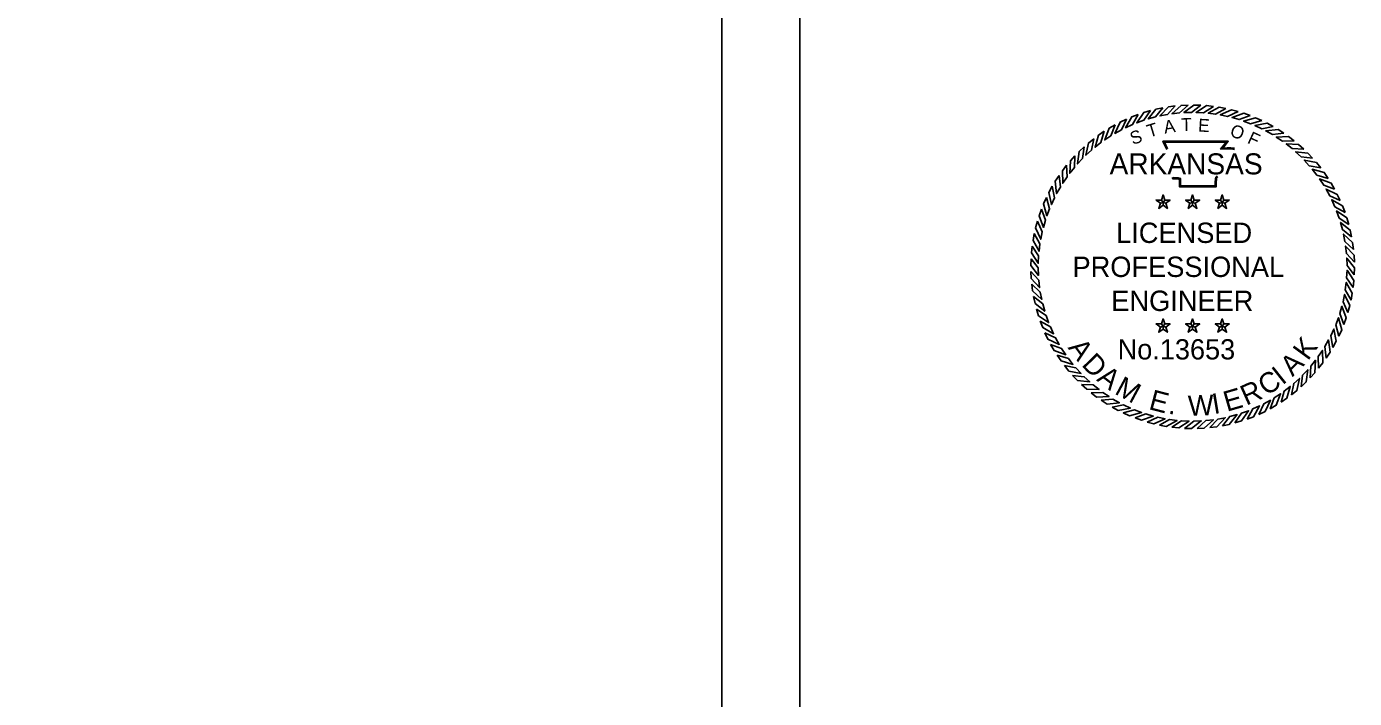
# Model space of a CAD drawing. Extents: x 759422 to 1467393, y 1662254 to 1691786.
# Drawn here: x 1466902.4 to 1467393.3, y 1691202.3 to 1691450.7 of the extents above; entities that cross this region are included whole.
import ezdxf

# ---------------------------------------------------------------- set-up
doc = ezdxf.new("R2010")
doc.units = 0
doc.layers.add('1', color=7, linetype='Continuous')
doc.layers.add('G-ANNO-STMP-AEW', color=7, linetype='Continuous')

msp = doc.modelspace()

# ---------------------------------------------------------------- linework, layer by layer
at = {"layer": '1'}
msp.add_line((1467159.42, 1690715.04), (1467159.42, 1691757.36), dxfattribs=at)
for points in [[(1467188.26, 1691786.2), (1465488.26, 1691786.2), (1465488.26, 1690686.2), (1467188.26, 1690686.2)], [(1465564.06, 1691757.36), (1465564.06, 1690715.04), (1467159.42, 1690715.04), (1467159.42, 1691693.36), (1466943.92, 1691693.36), (1466943.92, 1691707.96), (1466748.12, 1691707.96), (1466748.12, 1691757.36)]]:
    msp.add_lwpolyline(points, close=True, dxfattribs=at)
at = {"layer": 'G-ANNO-STMP-AEW'}
for points in [[(1467313.39, 1691418.23), (1467310.98, 1691417.31), (1467308.72, 1691413.32), (1467311.26, 1691414.47)], [(1467317.87, 1691419.63), (1467315.4, 1691418.91), (1467312.84, 1691415.11), (1467315.45, 1691416.05)], [(1467322.45, 1691420.68), (1467319.93, 1691420.15), (1467317.07, 1691416.56), (1467319.75, 1691417.3)], [(1467327.09, 1691421.36), (1467324.54, 1691421.03), (1467321.41, 1691417.68), (1467324.14, 1691418.2)], [(1467331.78, 1691421.68), (1467329.21, 1691421.55), (1467325.83, 1691418.46), (1467328.59, 1691418.76)], [(1467336.47, 1691421.63), (1467333.9, 1691421.71), (1467330.29, 1691418.88), (1467333.07, 1691418.97)], [(1467341.15, 1691421.21), (1467338.59, 1691421.49), (1467334.77, 1691418.96), (1467337.55, 1691418.83)], [(1467345.78, 1691420.43), (1467343.25, 1691420.9), (1467339.25, 1691418.68), (1467342, 1691418.33)], [(1467350.34, 1691419.28), (1467347.85, 1691419.96), (1467343.68, 1691418.05), (1467346.4, 1691417.49)], [(1467354.79, 1691417.79), (1467352.37, 1691418.65), (1467348.06, 1691417.08), (1467350.73, 1691416.31)], [(1467304.82, 1691414.39), (1467302.59, 1691413.11), (1467300.98, 1691408.81), (1467303.31, 1691410.34)], [(1467309.03, 1691416.48), (1467306.7, 1691415.38), (1467304.77, 1691411.22), (1467307.2, 1691412.56)], [(1467359.11, 1691415.94), (1467356.76, 1691416.99), (1467352.34, 1691415.77), (1467354.94, 1691414.79)], [(1467363.27, 1691413.77), (1467361.01, 1691415), (1467356.51, 1691414.12), (1467359.03, 1691412.94)], [(1467367.25, 1691411.27), (1467365.09, 1691412.67), (1467360.54, 1691412.16), (1467362.95, 1691410.78)], [(1467296.96, 1691409.26), (1467294.96, 1691407.64), (1467294.04, 1691403.15), (1467296.1, 1691405.02)], [(1467300.79, 1691411.98), (1467298.67, 1691410.53), (1467297.4, 1691406.12), (1467299.6, 1691407.82)], [(1467371.02, 1691408.47), (1467368.98, 1691410.04), (1467364.4, 1691409.88), (1467366.7, 1691408.32)], [(1467290, 1691402.96), (1467288.28, 1691401.05), (1467288.08, 1691396.47), (1467289.81, 1691398.64)], [(1467293.36, 1691406.25), (1467291.49, 1691404.48), (1467290.93, 1691399.93), (1467292.83, 1691401.96)], [(1467374.56, 1691405.38), (1467372.65, 1691407.1), (1467368.07, 1691407.3), (1467370.24, 1691405.57)], [(1467377.84, 1691402.02), (1467376.08, 1691403.89), (1467371.53, 1691404.45), (1467373.55, 1691402.55)], [(1467286.91, 1691399.42), (1467285.34, 1691397.39), (1467285.5, 1691392.8), (1467287.06, 1691395.1)], [(1467380.85, 1691398.42), (1467379.24, 1691400.42), (1467374.75, 1691401.34), (1467376.62, 1691399.28)], [(1467383.57, 1691394.59), (1467382.12, 1691396.71), (1467377.71, 1691397.98), (1467379.42, 1691395.78)], [(1467284.11, 1691395.65), (1467282.71, 1691393.5), (1467283.22, 1691388.94), (1467284.6, 1691391.36)], [(1467385.99, 1691390.56), (1467384.7, 1691392.79), (1467380.41, 1691394.4), (1467381.94, 1691392.07)], [(1467281.61, 1691391.68), (1467280.38, 1691389.42), (1467281.26, 1691384.92), (1467282.44, 1691387.43)], [(1467322.55, 1691385.71), (1467323.16, 1691386.56), (1467322.55, 1691388.45), (1467321.94, 1691386.56)], [(1467333.49, 1691385.71), (1467334.1, 1691386.56), (1467333.49, 1691388.45), (1467332.87, 1691386.56)], [(1467344.43, 1691385.71), (1467345.04, 1691386.56), (1467344.43, 1691388.45), (1467343.81, 1691386.56)], [(1467388.07, 1691386.35), (1467386.97, 1691388.68), (1467382.82, 1691390.61), (1467384.15, 1691388.18)], [(1467277.59, 1691383.19), (1467276.73, 1691380.77), (1467278.3, 1691376.46), (1467279.07, 1691379.13)], [(1467279.44, 1691387.51), (1467278.39, 1691385.17), (1467279.61, 1691380.75), (1467280.59, 1691383.35)], [(1467322.55, 1691385.71), (1467321.94, 1691386.56), (1467319.95, 1691386.56), (1467321.56, 1691385.39)], [(1467322.55, 1691385.71), (1467321.56, 1691385.39), (1467320.94, 1691383.5), (1467322.55, 1691384.67)], [(1467322.55, 1691385.71), (1467323.54, 1691385.39), (1467325.15, 1691386.56), (1467323.16, 1691386.56)], [(1467322.55, 1691385.71), (1467322.55, 1691384.67), (1467324.16, 1691383.5), (1467323.54, 1691385.39)], [(1467333.49, 1691385.71), (1467332.87, 1691386.56), (1467330.89, 1691386.56), (1467332.49, 1691385.39)], [(1467333.49, 1691385.71), (1467332.49, 1691385.39), (1467331.88, 1691383.5), (1467333.49, 1691384.67)], [(1467333.49, 1691385.71), (1467334.48, 1691385.39), (1467336.09, 1691386.56), (1467334.1, 1691386.56)], [(1467333.49, 1691385.71), (1467333.49, 1691384.67), (1467335.09, 1691383.5), (1467334.48, 1691385.39)], [(1467344.43, 1691385.71), (1467343.81, 1691386.56), (1467341.82, 1691386.56), (1467343.43, 1691385.39)], [(1467344.43, 1691385.71), (1467343.43, 1691385.39), (1467342.82, 1691383.5), (1467344.43, 1691384.67)], [(1467344.43, 1691385.71), (1467345.42, 1691385.39), (1467347.03, 1691386.56), (1467345.04, 1691386.56)], [(1467344.43, 1691385.71), (1467344.43, 1691384.67), (1467346.03, 1691383.5), (1467345.42, 1691385.39)], [(1467389.82, 1691381.99), (1467388.91, 1691384.4), (1467384.92, 1691386.66), (1467386.06, 1691384.12)], [(1467276.1, 1691378.74), (1467275.42, 1691376.26), (1467277.33, 1691372.09), (1467277.89, 1691374.81)], [(1467391.23, 1691377.51), (1467390.5, 1691379.98), (1467386.7, 1691382.54), (1467387.64, 1691379.93)], [(1467392.27, 1691372.93), (1467391.75, 1691375.45), (1467388.16, 1691378.31), (1467388.89, 1691375.63)], [(1467274.95, 1691374.19), (1467274.48, 1691371.66), (1467276.7, 1691367.65), (1467277.05, 1691370.41)], [(1467392.96, 1691368.29), (1467392.63, 1691370.84), (1467389.28, 1691373.97), (1467389.8, 1691371.24)], [(1467274.17, 1691369.56), (1467273.89, 1691367), (1467276.42, 1691363.18), (1467276.55, 1691365.95)], [(1467393.28, 1691363.6), (1467393.15, 1691366.17), (1467390.05, 1691369.55), (1467390.36, 1691366.79)], [(1467273.75, 1691364.88), (1467273.67, 1691362.31), (1467276.5, 1691358.7), (1467276.41, 1691361.47)], [(1467393.23, 1691358.91), (1467393.3, 1691361.48), (1467390.48, 1691365.09), (1467390.57, 1691362.31)], [(1467273.7, 1691360.18), (1467273.83, 1691357.61), (1467276.92, 1691354.23), (1467276.62, 1691357)], [(1467392.81, 1691354.23), (1467393.08, 1691356.79), (1467390.55, 1691360.61), (1467390.42, 1691357.83)], [(1467274.02, 1691355.5), (1467274.35, 1691352.95), (1467277.7, 1691349.82), (1467277.18, 1691352.55)], [(1467392.03, 1691349.6), (1467392.5, 1691352.12), (1467390.28, 1691356.13), (1467389.93, 1691353.38)], [(1467274.7, 1691350.85), (1467275.23, 1691348.33), (1467278.82, 1691345.48), (1467278.08, 1691348.16)], [(1467390.88, 1691345.04), (1467391.55, 1691347.53), (1467389.65, 1691351.7), (1467389.09, 1691348.98)], [(1467275.75, 1691346.27), (1467276.47, 1691343.8), (1467280.27, 1691341.24), (1467279.33, 1691343.86)], [(1467389.38, 1691340.59), (1467390.25, 1691343.01), (1467388.68, 1691347.32), (1467387.9, 1691344.65)], [(1467277.15, 1691341.79), (1467278.07, 1691339.39), (1467282.06, 1691337.13), (1467280.91, 1691339.66)], [(1467322.55, 1691339.91), (1467321.94, 1691340.75), (1467319.95, 1691340.75), (1467321.56, 1691339.59)], [(1467322.55, 1691339.91), (1467321.56, 1691339.59), (1467320.94, 1691337.7), (1467322.55, 1691338.87)], [(1467322.55, 1691339.91), (1467323.16, 1691340.75), (1467322.55, 1691342.64), (1467321.94, 1691340.75)], [(1467322.55, 1691339.91), (1467323.54, 1691339.59), (1467325.15, 1691340.75), (1467323.16, 1691340.75)], [(1467322.55, 1691339.91), (1467322.55, 1691338.87), (1467324.16, 1691337.7), (1467323.54, 1691339.59)], [(1467333.49, 1691339.91), (1467332.87, 1691340.75), (1467330.89, 1691340.75), (1467332.49, 1691339.59)], [(1467333.49, 1691339.91), (1467332.49, 1691339.59), (1467331.88, 1691337.7), (1467333.49, 1691338.87)], [(1467333.49, 1691339.91), (1467334.1, 1691340.75), (1467333.49, 1691342.64), (1467332.87, 1691340.75)], [(1467333.49, 1691339.91), (1467334.48, 1691339.59), (1467336.09, 1691340.75), (1467334.1, 1691340.75)], [(1467333.49, 1691339.91), (1467333.49, 1691338.87), (1467335.09, 1691337.7), (1467334.48, 1691339.59)], [(1467344.43, 1691339.91), (1467343.81, 1691340.75), (1467341.82, 1691340.75), (1467343.43, 1691339.59)], [(1467344.43, 1691339.91), (1467343.43, 1691339.59), (1467342.82, 1691337.7), (1467344.43, 1691338.87)], [(1467344.43, 1691339.91), (1467345.04, 1691340.75), (1467344.43, 1691342.64), (1467343.81, 1691340.75)], [(1467344.43, 1691339.91), (1467345.42, 1691339.59), (1467347.03, 1691340.75), (1467345.04, 1691340.75)], [(1467344.43, 1691339.91), (1467344.43, 1691338.87), (1467346.03, 1691337.7), (1467345.42, 1691339.59)], [(1467387.54, 1691336.27), (1467388.59, 1691338.62), (1467387.36, 1691343.04), (1467386.38, 1691340.44)], [(1467278.9, 1691337.43), (1467280, 1691335.11), (1467284.16, 1691333.17), (1467282.82, 1691335.61)], [(1467382.86, 1691328.13), (1467384.27, 1691330.29), (1467383.75, 1691334.84), (1467382.37, 1691332.43)], [(1467385.36, 1691332.11), (1467386.59, 1691334.37), (1467385.72, 1691338.87), (1467384.54, 1691336.35)], [(1467280.99, 1691333.22), (1467282.27, 1691330.99), (1467286.57, 1691329.39), (1467285.04, 1691331.71)], [(1467283.4, 1691329.19), (1467284.85, 1691327.07), (1467289.26, 1691325.81), (1467287.56, 1691328)], [(1467380.06, 1691324.36), (1467381.63, 1691326.4), (1467381.47, 1691330.98), (1467379.91, 1691328.68)], [(1467286.12, 1691325.37), (1467287.74, 1691323.36), (1467292.23, 1691322.45), (1467290.36, 1691324.5)], [(1467376.97, 1691320.82), (1467378.7, 1691322.73), (1467378.9, 1691327.31), (1467377.16, 1691325.14)], [(1467289.13, 1691321.76), (1467290.9, 1691319.89), (1467295.45, 1691319.33), (1467293.42, 1691321.23)], [(1467370.01, 1691314.53), (1467372.02, 1691316.14), (1467372.93, 1691320.63), (1467370.88, 1691318.76)], [(1467373.62, 1691317.54), (1467375.49, 1691319.3), (1467376.05, 1691323.85), (1467374.15, 1691321.83)], [(1467292.42, 1691318.41), (1467294.33, 1691316.68), (1467298.91, 1691316.48), (1467296.74, 1691318.22)], [(1467295.96, 1691315.32), (1467297.99, 1691313.75), (1467302.58, 1691313.91), (1467300.28, 1691315.47)], [(1467362.16, 1691309.39), (1467364.39, 1691310.68), (1467365.99, 1691314.97), (1467363.67, 1691313.44)], [(1467366.19, 1691311.81), (1467368.31, 1691313.26), (1467369.57, 1691317.66), (1467367.38, 1691315.96)], [(1467299.73, 1691312.52), (1467301.88, 1691311.11), (1467306.44, 1691311.63), (1467304.02, 1691313.01)], [(1467303.7, 1691310.02), (1467305.96, 1691308.79), (1467310.46, 1691309.66), (1467307.95, 1691310.84)], [(1467353.59, 1691305.56), (1467355.99, 1691306.47), (1467358.25, 1691310.46), (1467355.72, 1691309.32)], [(1467357.95, 1691307.31), (1467360.27, 1691308.41), (1467362.21, 1691312.56), (1467359.77, 1691311.23)], [(1467307.87, 1691307.84), (1467310.21, 1691306.79), (1467314.63, 1691308.02), (1467312.03, 1691309)], [(1467312.19, 1691306), (1467314.61, 1691305.13), (1467318.92, 1691306.7), (1467316.25, 1691307.48)], [(1467316.64, 1691304.5), (1467319.12, 1691303.83), (1467323.29, 1691305.73), (1467320.57, 1691306.29)], [(1467321.19, 1691303.35), (1467323.72, 1691302.88), (1467327.73, 1691305.1), (1467324.97, 1691305.45)], [(1467325.82, 1691302.57), (1467328.38, 1691302.3), (1467332.2, 1691304.83), (1467329.43, 1691304.96)], [(1467330.5, 1691302.15), (1467333.07, 1691302.08), (1467336.68, 1691304.9), (1467333.91, 1691304.81)], [(1467335.2, 1691302.1), (1467337.77, 1691302.23), (1467341.15, 1691305.33), (1467338.38, 1691305.02)], [(1467339.88, 1691302.42), (1467342.43, 1691302.75), (1467345.56, 1691306.1), (1467342.83, 1691305.58)], [(1467344.53, 1691303.11), (1467347.05, 1691303.63), (1467349.9, 1691307.22), (1467347.22, 1691306.49)], [(1467349.11, 1691304.15), (1467351.58, 1691304.88), (1467354.14, 1691308.68), (1467351.52, 1691307.74)]]:
    msp.add_lwpolyline(points, close=True, dxfattribs=at)
for points in [[(1467323.9, 1691405.31), (1467322.51, 1691408.32), (1467346.64, 1691408.34), (1467344.62, 1691405.81), (1467346.26, 1691405.83), (1467347.63, 1691405.85), (1467349, 1691405.7)], [(1467324.25, 1691405.47), (1467323.11, 1691407.94), (1467345.84, 1691407.96), (1467343.82, 1691405.41), (1467346.26, 1691405.45), (1467347.61, 1691405.46), (1467348.96, 1691405.32)], [(1467342.83, 1691395.19), (1467342.42, 1691394.86), (1467342.29, 1691394.36), (1467342.15, 1691393.11), (1467342.15, 1691391.44), (1467328.68, 1691391.44), (1467328.68, 1691393.69), (1467328.68, 1691394.19), (1467328.14, 1691394.36), (1467326.22, 1691394.36), (1467325.88, 1691394.88)], [(1467342.59, 1691395.49), (1467342.09, 1691395.08), (1467341.91, 1691394.43), (1467341.77, 1691393.13), (1467341.77, 1691391.82), (1467329.06, 1691391.82), (1467329.06, 1691393.69), (1467329.06, 1691394.48), (1467328.19, 1691394.74), (1467326.43, 1691394.74), (1467326.2, 1691395.09)]]:
    msp.add_lwpolyline(points, dxfattribs=at)

# ---------------------------------------------------------------- texts
for s, height, rotation, p in [('T', 4.76, 16.9015, (1467317.39, 1691409.6)), ('A', 4.76, 8.6788, (1467323.17, 1691411.11)), ('T', 4.76, 1.4789, (1467329.32, 1691412.06)), ('E', 4.76, 356.672, (1467335.41, 1691411.92)), ('O', 4.76, 341.2218, (1467346.96, 1691410.28)), ('S', 4.76, 19.7726, (1467311.34, 1691406.89)), ('F', 4.76, 335.3628, (1467353.38, 1691407.78)), ('A', 7.52, 305.982, (1467287.21, 1691331.96)), ('K', 7.52, 53.8471, (1467376.08, 1691326.9)), ('D', 7.52, 314.3022, (1467292.14, 1691325.46)), ('A', 7.52, 322.6223, (1467297.72, 1691319.96)), ('I', 7.52, 38.4057, (1467366.65, 1691317.95)), ('A', 7.52, 45.185, (1467370.44, 1691321)), ('M', 7.52, 331.7969, (1467304.28, 1691315.1)), ('R', 7.52, 24.1616, (1467353.31, 1691310.46)), ('C', 7.52, 32.1396, (1467360.67, 1691313.98)), ('E', 7.52, 345.2782, (1467316.95, 1691309.33)), ('W', 7.52, 2.1127, (1467331.9, 1691306.76)), ('I', 7.52, 9.5753, (1467341.34, 1691307.4)), ('E', 7.52, 16.0125, (1467346.14, 1691308.26)), ('.', 7.52, 350.8583, (1467324.26, 1691307.63))]:
    msp.add_text(s, height=height, rotation=rotation, dxfattribs=at).set_placement(p)
for s, height, p in [('ARKANSAS', 7.767, (1467302.79, 1691396.06)), ('LICENSED', 7.52, (1467305.2, 1691370.71)), ('PROFESSIONAL', 7.5196, (1467289.09, 1691358.13)), ('ENGINEER', 7.52, (1467303.41, 1691345.56)), ('No.13653', 7.49, (1467305.78, 1691327.63))]:
    msp.add_text(s, height=height, dxfattribs=at).set_placement(p)

doc.saveas('drawing.dxf')
